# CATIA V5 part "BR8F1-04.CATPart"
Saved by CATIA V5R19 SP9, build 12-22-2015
Part number: BR8F1-04
Definition: design
Nomenclature: BR8F1-04
Source: Unknown
Bounding box of the stored display mesh (mm): x -3.9 to 11.15, y 0 to 18.1, z 0 to 20.32
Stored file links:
  Z:\charly_robot\BR8F1-04.CATPart
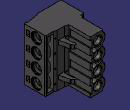
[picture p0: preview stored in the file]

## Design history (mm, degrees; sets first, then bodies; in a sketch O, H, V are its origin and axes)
AxisSystem1: origin (0, 0, 0), X (1, 0, 0), Y (0, 1, 0), Z (0, 0, 1)
Body1 "MANIFOLD_SOLID_BREP #59229" (main body)
  Solid1: solid without history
